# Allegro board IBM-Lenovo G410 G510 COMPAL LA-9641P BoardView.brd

Outline 212.65 x 184.36 mm; copper layers: TOP, VCC, IN1, IN2, GND, BOTTOM. Coordinates in mm from the lower left corner of the outline.
Outline path: 126,40.45 126,23.8 ; 126,40.45 arc(126.88,42.57) 129,43.45 ; 126,40.45 126,23.8 ; 126,23.8 arc(126.88,21.68) 129,20.8 ; 129,43.45 133.63,43.45 ; 129,43.45 133.63,43.45 ; 133.63,43.45 arc(134.34,43.74) 134.63,44.45 ; 129,20.8 176.5,20.8 ; 129,20.8 176.5,20.8 ; 176.5,20.8 arc(178.62,21.68) 179.5,23.8 ; 134.63,50.59 134.63,44.45 ; 134.63,50.59 arc(135.51,52.71) 137.63,53.59 ; 134.63,50.59 134.63,44.45 ; 137.63,53.59 142,53.59 ; 137.63,53.59 142,53.59 ; 142,53.59 arc(144.12,52.71) 145,50.59 ; 145,50.59 145,41.4 ; 145,50.59 145,41.4 ; 145,41.4 arc(145.29,40.69) 146,40.4 ; 146,40.4 163.7,40.4 ; 146,40.4 163.7,40.4 ; 163.7,40.4 arc(164.41,40.69) 164.7,41.4 ; 164.7,50.59 164.7,41.4 ; 164.7,50.59 arc(165.58,52.71) 167.7,53.59 ; 164.7,50.59 164.7,41.4 ; 167.7,53.59 170.7,53.59 ; 167.7,53.59 170.7,53.59 ; 170.7,53.59 arc(172.82,52.71) 173.7,50.59 ; 173.7,50.59 173.7,37.65 ; 173.7,50.59 173.7,37.65 ; 173.7,37.65 arc(173.99,36.94) 174.7,36.65 ; 174.7,36.65 176.5,36.65 ; 174.7,36.65 176.5,36.65 ; 176.5,36.65 arc(178.62,35.77) 179.5,33.65 ; 179.5,33.65 179.5,23.8 ; 179.5,33.65 179.5,23.8 ; 0,107.15 arc(0.29,107.86) 1,108.15 3.65,108.15 3.65,110.15 5.05,110.15 arc(6.05,111.15) 5.05,112.15 5.05,125.15 arc(6.05,126.15) 5.05,127.15 3.65,127.15 3.65,130 arc(3.94,130.71) 4.65,131 34.7,131 arc(35.41,131.29) 35.7,132 arc(35.99,132.71) 36.7,133 61.54,133 arc(62.25,133.29) 62.54,134 62.54,134.39 arc(62.74,134.98) 63.25,135.34 arc(68.65,137.48) 73.62,140.47 arc(88.26,151.25) 95.65,167.87 arc(95.99,168.47) 96.64,168.71 106.23,168.71 arc(106.93,169) 107.23,169.71 107.23,178.5 arc(107.52,179.21) 108.23,179.5 172.75,179.5 arc(173.46,179.79) 173.75,180.5 173.75,181.36 arc(174.04,182.07) 174.75,182.36 175.75,182.36 arc(176.46,182.65) 176.75,183.36 arc(177.04,184.07) 177.75,184.36 207.5,184.36 arc(208.21,184.07) 208.5,183.36 208.5,180.5 arc(208.79,179.79) 209.5,179.5 212.65,179.5 212.65,139.05 209.69,136.09 arc(209.37,135.88) 208.99,135.8 204.1,135.8 arc(203.39,135.51) 203.1,134.8 203.1,108.25 202.1,108.25 202.1,77.25 203.1,77.25 203.1,66.95 203.5,66.95 203.5,37.95 203.1,37.95 203.1,30.2 arc(203.39,29.49) 204.1,29.2 212.65,29.2 212.65,5.15 211.4,5.15 arc(210.41,4.74) 210,3.75 210,1.92 arc(209.56,1.55) 209.4,1 209.4,0 27.33,0 arc(26.77,0.58) 26,0.8 25,0.8 arc(24.23,0.58) 23.67,0 5.65,0 arc(5.14,0.22) 4.6,0.3 3.65,0.3 arc(1.53,1.18) 0.65,3.3 0.65,5.13 arc(0.94,5.83) 1.65,6.13 12.2,6.13 12.2,16.38 1.65,16.38 arc(0.94,16.67) 0.65,17.38 0.65,19.31 arc(0.94,20.02) 1.65,20.31 12.02,20.31 arc(13.02,21.31) 12.02,22.31 12.02,31.81 arc(13.02,32.81) 12.02,33.81 3.37,33.81 arc(2.66,34.1) 2.37,34.81 2.37,40.31 arc(2.66,41.02) 3.37,41.31 12.02,41.31 arc(13.02,42.31) 12.02,43.31 12.02,52.81 arc(13.02,53.81) 12.02,54.81 2.24,54.81 arc(1.53,55.1) 1.24,55.81 1.24,60.31 arc(1.53,61.02) 2.24,61.31 7.34,61.31 arc(8.34,60.31) 9.34,61.31 9.34,76.81 arc(8.34,77.81) 7.34,76.81 1.1,76.81 arc(0.39,77.1) 0.1,77.81 0.1,80.29 arc(0.39,80.99) 1.1,81.29 8.7,81.29 arc(10.41,80.58) 9.7,82.29 9.7,96.88 arc(10.41,98.59) 8.7,97.88 1,97.88 arc(0.29,98.18) 0,98.88 0,107.15

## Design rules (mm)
net group CLK_PCIE_VGA: nets CLK_PCIE_VGA CLK_PCIE_VGA#
net group CLK_PCIE_VGA_R: nets CLK_PCIE_VGA#_R CLK_PCIE_VGA_R
net group CLKA0: nets CLKA0 CLKA0#
net group CLKA1: nets CLKA1 CLKA1#
net group CLKB0: nets CLKB0 CLKB0#
net group CLKB1: nets CLKB1 CLKB1#
net group DDR_A_DQS0: nets DDR_A_DQS0 DDR_A_DQS#0
net group DDR_A_DQS1: nets DDR_A_DQS1 DDR_A_DQS#1
net group DDR_A_DQS2: nets DDR_A_DQS2 DDR_A_DQS#2
net group DDR_A_DQS3: nets DDR_A_DQS3 DDR_A_DQS#3
net group DDR_A_DQS4: nets DDR_A_DQS4 DDR_A_DQS#4
net group DDR_A_DQS5: nets DDR_A_DQS5 DDR_A_DQS#5
net group DDR_A_DQS6: nets DDR_A_DQS6 DDR_A_DQS#6
net group DDR_A_DQS7: nets DDR_A_DQS7 DDR_A_DQS#7
net group DDR_B_DQS0: nets DDR_B_DQS0 DDR_B_DQS#0
net group DDR_B_DQS1: nets DDR_B_DQS1 DDR_B_DQS#1
net group DDR_B_DQS2: nets DDR_B_DQS2 DDR_B_DQS#2
net group DDR_B_DQS3: nets DDR_B_DQS3 DDR_B_DQS#3
net group DDR_B_DQS4: nets DDR_B_DQS4 DDR_B_DQS#4
net group DDR_B_DQS5: nets DDR_B_DQS5 DDR_B_DQS#5
net group DDR_B_DQS6: nets DDR_B_DQS6 DDR_B_DQS#6
net group DDR_B_DQS7: nets DDR_B_DQS7 DDR_B_DQS#7
net group DIFFPAIR0: nets N25318268 N25318300
net group DMI_CRX_PTX_0: nets DMI_CRX_PTX_N0 DMI_CRX_PTX_P0
net group DMI_CRX_PTX_1: nets DMI_CRX_PTX_N1 DMI_CRX_PTX_P1
net group DMI_CRX_PTX_2: nets DMI_CRX_PTX_N2 DMI_CRX_PTX_P2
net group DMI_CRX_PTX_3: nets DMI_CRX_PTX_N3 DMI_CRX_PTX_P3
net group DMI_CTX_PRX_0: nets DMI_CTX_PRX_N0 DMI_CTX_PRX_P0
net group DMI_CTX_PRX_1: nets DMI_CTX_PRX_N1 DMI_CTX_PRX_P1
net group DMI_CTX_PRX_2: nets DMI_CTX_PRX_N2 DMI_CTX_PRX_P2
net group DMI_CTX_PRX_3: nets DMI_CTX_PRX_N3 DMI_CTX_PRX_P3
net group EC_SMB_CK1: nets EC_SMB_CK1 EC_SMB_DA1
net group EC_SMCA: nets EC_SMCA EC_SMDA
net group EDP_CPU_AUX: nets EDP_CPU_AUX EDP_CPU_AUX#
net group EDP_CPU_AUX_R: nets EDP_CPU_AUX#_R EDP_CPU_AUX_R
net group EDP_CPU_LANE_0: nets EDP_CPU_LANE_N0 EDP_CPU_LANE_P0
net group EDP_CPU_LANE_0_R: nets EDP_CPU_LANE_N0_R EDP_CPU_LANE_P0_R
net group EDP_CPU_LANE_1: nets EDP_CPU_LANE_N1 EDP_CPU_LANE_P1
net group FDI_CTX_PRX_0: nets FDI_CTX_PRX_N0 FDI_CTX_PRX_P0
net group FDI_CTX_PRX_1: nets FDI_CTX_PRX_N1 FDI_CTX_PRX_P1
net group HDMI_CLK_CK: nets HDMI_CLK+_CK HDMI_CLK-_CK
net group HDMI_CLK_CONN: nets HDMI_CLK+_CONN HDMI_CLK-_CONN
net group HDMI_TX0_CK: nets HDMI_TX0+_CK HDMI_TX0-_CK
net group HDMI_TX0_CONN: nets HDMI_TX0+_CONN HDMI_TX0-_CONN
net group HDMI_TX1_CK: nets HDMI_TX1+_CK HDMI_TX1-_CK
net group HDMI_TX1_CONN: nets HDMI_TX1+_CONN HDMI_TX1-_CONN
net group HDMI_TX2_CK: nets HDMI_TX2+_CK HDMI_TX2-_CK
net group HDMI_TX2_CONN: nets HDMI_TX2+_CONN HDMI_TX2-_CONN
net group HDMICLK_NB: nets HDMICLK_NB HDMIDAT_NB
net group HDMICLK_R: nets HDMICLK_R HDMIDAT_R
net group HP: nets HP_L HP_R
net group HPOUT: nets HPOUT_L HPOUT_R
net group LVDS_A0: nets LVDS_A0 LVDS_A0#
net group LVDS_A1: nets LVDS_A1 LVDS_A1#
net group LVDS_A2: nets LVDS_A2 LVDS_A2#
net group LVDS_ACLK: nets LVDS_ACLK LVDS_ACLK#
net group M_CLK_DDR0: nets M_CLK_DDR0 M_CLK_DDR#0
net group M_CLK_DDR1: nets M_CLK_DDR1 M_CLK_DDR#1
net group M_CLK_DDR2: nets M_CLK_DDR2 M_CLK_DDR#2
net group M_CLK_DDR3: nets M_CLK_DDR3 M_CLK_DDR#3
net group MDI0: nets MDI0+ MDI0-
net group MDI1: nets MDI1+ MDI1-
net group MICB: nets MICB_L MICB_R
net group MIIC_SCL: nets MIIC_SCL MIIC_SDA
net group PCH_SMBCLK: nets PCH_SMBCLK PCH_SMBDATA
net group PCIE_CRX_C_GTX_0: nets PCIE_CRX_C_GTX_N0 PCIE_CRX_C_GTX_P0
net group PCIE_CRX_C_GTX_1: nets PCIE_CRX_C_GTX_N1 PCIE_CRX_C_GTX_P1
net group PCIE_CRX_C_GTX_2: nets PCIE_CRX_C_GTX_N2 PCIE_CRX_C_GTX_P2
net group PCIE_CRX_C_GTX_3: nets PCIE_CRX_C_GTX_N3 PCIE_CRX_C_GTX_P3
net group PCIE_CRX_C_GTX_4: nets PCIE_CRX_C_GTX_N4 PCIE_CRX_C_GTX_P4
net group PCIE_CRX_C_GTX_5: nets PCIE_CRX_C_GTX_N5 PCIE_CRX_C_GTX_P5
net group PCIE_CRX_C_GTX_6: nets PCIE_CRX_C_GTX_N6 PCIE_CRX_C_GTX_P6
net group PCIE_CRX_C_GTX_7: nets PCIE_CRX_C_GTX_N7 PCIE_CRX_C_GTX_P7
net group PCIE_CRX_GTX_0: nets PCIE_CRX_GTX_N0 PCIE_CRX_GTX_P0
net group PCIE_CRX_GTX_1: nets PCIE_CRX_GTX_N1 PCIE_CRX_GTX_P1
net group PCIE_CRX_GTX_2: nets PCIE_CRX_GTX_N2 PCIE_CRX_GTX_P2
net group PCIE_CRX_GTX_3: nets PCIE_CRX_GTX_N3 PCIE_CRX_GTX_P3
net group PCIE_CRX_GTX_4: nets PCIE_CRX_GTX_N4 PCIE_CRX_GTX_P4
net group PCIE_CRX_GTX_5: nets PCIE_CRX_GTX_N5 PCIE_CRX_GTX_P5
net group PCIE_CRX_GTX_6: nets PCIE_CRX_GTX_N6 PCIE_CRX_GTX_P6
net group PCIE_CRX_GTX_7: nets PCIE_CRX_GTX_N7 PCIE_CRX_GTX_P7
net group PCIE_CTX_GRX_0: nets PCIE_CTX_GRX_N0 PCIE_CTX_GRX_P0
net group PCIE_CTX_GRX_1: nets PCIE_CTX_GRX_N1 PCIE_CTX_GRX_P1
net group PCIE_CTX_GRX_2: nets PCIE_CTX_GRX_N2 PCIE_CTX_GRX_P2
net group PCIE_CTX_GRX_3: nets PCIE_CTX_GRX_N3 PCIE_CTX_GRX_P3
net group PCIE_CTX_GRX_4: nets PCIE_CTX_GRX_N4 PCIE_CTX_GRX_P4
net group PCIE_CTX_GRX_5: nets PCIE_CTX_GRX_N5 PCIE_CTX_GRX_P5
net group PCIE_CTX_GRX_6: nets PCIE_CTX_GRX_N6 PCIE_CTX_GRX_P6
net group PCIE_CTX_GRX_7: nets PCIE_CTX_GRX_N7 PCIE_CTX_GRX_P7
net group PCIE_CTX_GRX_C_0: nets PCIE_CTX_GRX_C_N0 PCIE_CTX_GRX_C_P0
net group PCIE_CTX_GRX_C_1: nets PCIE_CTX_GRX_C_N1 PCIE_CTX_GRX_C_P1
net group PCIE_CTX_GRX_C_2: nets PCIE_CTX_GRX_C_N2 PCIE_CTX_GRX_C_P2
net group PCIE_CTX_GRX_C_3: nets PCIE_CTX_GRX_C_N3 PCIE_CTX_GRX_C_P3
net group PCIE_CTX_GRX_C_4: nets PCIE_CTX_GRX_C_N4 PCIE_CTX_GRX_C_P4
net group PCIE_CTX_GRX_C_5: nets PCIE_CTX_GRX_C_N5 PCIE_CTX_GRX_C_P5
net group PCIE_CTX_GRX_C_6: nets PCIE_CTX_GRX_C_N6 PCIE_CTX_GRX_C_P6
net group PCIE_CTX_GRX_C_7: nets PCIE_CTX_GRX_C_N7 PCIE_CTX_GRX_C_P7
net group PCIE_PRX_C_DTX_3: nets PCIE_PRX_C_DTX_N3 PCIE_PRX_C_DTX_P3
net group QSA0: nets QSA0 QSA#0
net group QSA1: nets QSA1 QSA#1
net group QSA2: nets QSA2 QSA#2
net group QSA3: nets QSA3 QSA#3
net group QSA4: nets QSA4 QSA#4
net group QSA5: nets QSA5 QSA#5
net group QSA6: nets QSA6 QSA#6
net group QSA7: nets QSA7 QSA#7
net group QSB0: nets QSB0 QSB#0
net group QSB1: nets QSB1 QSB#1
net group QSB2: nets QSB2 QSB#2
net group QSB3: nets QSB3 QSB#3
net group QSB4: nets QSB4 QSB#4
net group QSB5: nets QSB5 QSB#5
net group QSB6: nets QSB6 QSB#6
net group QSB7: nets QSB7 QSB#7
net group SML1CLK: nets SML1CLK SML1DATA
net group SPK_L: nets SPK_L1- SPK_L2+
net group SPK_L_CONN: nets SPK_L1-_CONN SPK_L2+_CONN
net group SPK_R: nets SPK_R1- SPK_R2+
net group SPK_R_CONN: nets SPK_R1-_CONN SPK_R2+_CONN
net group TMDS_B_CLK_PCH: nets TMDS_B_CLK#_PCH TMDS_B_CLK_PCH
net group TMDS_B_DATA0_PCH: nets TMDS_B_DATA0#_PCH TMDS_B_DATA0_PCH
net group TMDS_B_DATA1_PCH: nets TMDS_B_DATA1#_PCH TMDS_B_DATA1_PCH
net group TMDS_B_DATA2_PCH: nets TMDS_B_DATA2#_PCH TMDS_B_DATA2_PCH
net group U2D2: nets U2DN2 U2DP2
net group U3RXD1: nets U3RXDN1 U3RXDP1
net group U3RXD2: nets U3RXDN2 U3RXDP2
net group U3TXD1: nets U3TXDN1 U3TXDP1
net group U3TXD1_L: nets U3TXDN1_L U3TXDP1_L
net group U3TXD2: nets U3TXDN2 U3TXDP2
net group U3TXD2_L: nets U3TXDN2_L U3TXDP2_L
net group USB3_RX1_: nets USB3_RX1_N USB3_RX1_P
net group USB3_RX2_: nets USB3_RX2_N USB3_RX2_P
net group USB3_TX1_: nets USB3_TX1_N USB3_TX1_P
net group USB3_TX2_: nets USB3_TX2_N USB3_TX2_P
net group USB20_0: nets USB20_N0 USB20_P0
net group USB20_1: nets USB20_N1 USB20_P1
net group USB20_2: nets USB20_N2 USB20_P2
net group USB20_3_R: nets USB20_N3_R USB20_P3_R
net group USB20_9: nets USB20_N9 USB20_P9
net group USB20_9_C: nets USB20_N9_C USB20_P9_C
net group USB20_10: nets USB20_N10 USB20_P10
net group USB20_11: nets USB20_N11 USB20_P11
net group USB20_11_R: nets USB20_N11_R USB20_P11_R
net group VGA_SMB_CK2: nets VGA_SMB_CK2 VGA_SMB_DA2
net group VRAMA-CS#: nets CSA0#_0 CSA1#_0
net group VRAMB-CS#: nets CSB0#_0 CSB1#_0
net group 12/13.5: nets BUF_CPU_RST# CPU_PLTRST# DDR3_DRAMRST# H_DRAMRST# H_PM_SYNC H_PM_SYNC_R H_PROCHOT# H_PROCHOT#_R
net group 18: nets H_PECI
net group CRT-DAC: nets BLUE DAC_BLU DAC_GRN DAC_RED GREEN RED
net group CRT-SYNC: nets CRT_HSYNC CRT_VSYNC JVGA_HS JVGA_VS
net group DDRA-ADD: nets DDR_A_BS0 DDR_A_BS1 DDR_A_BS2 DDR_A_CAS# DDR_A_MA0 DDR_A_MA1 DDR_A_MA2 DDR_A_MA3 DDR_A_MA4 DDR_A_MA5 DDR_A_MA6 DDR_A_MA7 DDR_A_MA8 DDR_A_MA9 DDR_A_MA10 DDR_A_MA11 DDR_A_MA12 DDR_A_MA13 DDR_A_MA14 DDR_A_MA15 DDR_A_RAS# DDR_A_WE#
net group DDRA-CTL: nets DDR_CKE0_DIMMA DDR_CKE1_DIMMA DDR_CS0_DIMMA# DDR_CS1_DIMMA# M_ODT0 M_ODT1
net group DDRA_D0: nets DDR_A_D0 DDR_A_D1 DDR_A_D2 DDR_A_D3 DDR_A_D4 DDR_A_D5 DDR_A_D6 DDR_A_D7
net group DDRA_D1: nets DDR_A_D8 DDR_A_D9 DDR_A_D10 DDR_A_D11 DDR_A_D12 DDR_A_D13 DDR_A_D14 DDR_A_D15
net group DDRA_D2: nets DDR_A_D16 DDR_A_D17 DDR_A_D18 DDR_A_D19 DDR_A_D20 DDR_A_D21 DDR_A_D22 DDR_A_D23
net group DDRA_D3: nets DDR_A_D24 DDR_A_D25 DDR_A_D26 DDR_A_D27 DDR_A_D28 DDR_A_D29 DDR_A_D30 DDR_A_D31
net group DDRA_D4: nets DDR_A_D32 DDR_A_D33 DDR_A_D34 DDR_A_D35 DDR_A_D36 DDR_A_D37 DDR_A_D38 DDR_A_D39
net group DDRA_D5: nets DDR_A_D40 DDR_A_D41 DDR_A_D42 DDR_A_D43 DDR_A_D44 DDR_A_D45 DDR_A_D46 DDR_A_D47
net group DDRA_D6: nets DDR_A_D48 DDR_A_D49 DDR_A_D50 DDR_A_D51 DDR_A_D52 DDR_A_D53 DDR_A_D54 DDR_A_D55
net group DDRA_D7: nets DDR_A_D56 DDR_A_D57 DDR_A_D58 DDR_A_D59 DDR_A_D60 DDR_A_D61 DDR_A_D62 DDR_A_D63
net group DDRB-ADD: nets DDR_B_BS0 DDR_B_BS1 DDR_B_BS2 DDR_B_CAS# DDR_B_MA0 DDR_B_MA1 DDR_B_MA2 DDR_B_MA3 DDR_B_MA4 DDR_B_MA5 DDR_B_MA6 DDR_B_MA7 DDR_B_MA8 DDR_B_MA9 DDR_B_MA10 DDR_B_MA11 DDR_B_MA12 DDR_B_MA13 DDR_B_MA14 DDR_B_MA15 DDR_B_RAS# DDR_B_WE#
net group DDRB-CTL: nets DDR_CKE2_DIMMB DDR_CKE3_DIMMB DDR_CS2_DIMMB# DDR_CS3_DIMMB# M_ODT2 M_ODT3
net group DDRB_D0: nets DDR_B_D0 DDR_B_D1 DDR_B_D2 DDR_B_D3 DDR_B_D4 DDR_B_D5 DDR_B_D6 DDR_B_D7
net group DDRB_D1: nets DDR_B_D8 DDR_B_D9 DDR_B_D10 DDR_B_D11 DDR_B_D12 DDR_B_D13 DDR_B_D14 DDR_B_D15
net group DDRB_D2: nets DDR_B_D16 DDR_B_D17 DDR_B_D18 DDR_B_D19 DDR_B_D20 DDR_B_D21 DDR_B_D22 DDR_B_D23
net group DDRB_D3: nets DDR_B_D24 DDR_B_D25 DDR_B_D26 DDR_B_D27 DDR_B_D28 DDR_B_D29 DDR_B_D30 DDR_B_D31
net group DDRB_D4: nets DDR_B_D32 DDR_B_D33 DDR_B_D34 DDR_B_D35 DDR_B_D36 DDR_B_D37 DDR_B_D38 DDR_B_D39
net group DDRB_D5: nets DDR_B_D40 DDR_B_D41 DDR_B_D42 DDR_B_D43 DDR_B_D44 DDR_B_D45 DDR_B_D46 DDR_B_D47
net group DDRB_D6: nets DDR_B_D48 DDR_B_D49 DDR_B_D50 DDR_B_D51 DDR_B_D52 DDR_B_D53 DDR_B_D54 DDR_B_D55
net group DDRB_D7: nets DDR_B_D56 DDR_B_D57 DDR_B_D58 DDR_B_D59 DDR_B_D60 DDR_B_D61 DDR_B_D62 DDR_B_D63
net group HDA: nets HDA_BIT_CLK HDA_BITCLK_AUDIO HDA_RST# HDA_RST_AUDIO# HDA_SDIN0 HDA_SDOUT_AUDIO HDA_SPKR HDA_SYNC HDA_SYNC_AUDIO
net group LAN-10/10: nets MDO0+ MDO0- MDO1+ MDO1-
net group LPC: nets LPC_AD0 LPC_AD1 LPC_AD2 LPC_AD3 LPC_FRAME# SERIRQ
net group PCIE: nets PCIE_PRX_DTX_N2 PCIE_PRX_DTX_N3 PCIE_PRX_DTX_P2 PCIE_PRX_DTX_P3 PCIE_PTX_C_DRX_N2 PCIE_PTX_C_DRX_N3 PCIE_PTX_C_DRX_P2 PCIE_PTX_C_DRX_P3 PCIE_PTX_DRX_N2 PCIE_PTX_DRX_N3 PCIE_PTX_DRX_P2 PCIE_PTX_DRX_P3
net group PLATFORM-CLK: nets CLK_BUF_BCLK CLK_BUF_BCLK# CLK_BUF_CKSSCD CLK_BUF_CKSSCD# CLK_BUF_DMI CLK_BUF_DMI# CLK_BUF_DOT96 CLK_BUF_DOT96# CLK_CPU_DMI CLK_CPU_DMI# CLK_CPU_DPLL CLK_CPU_DPLL# CLK_CPU_SSC_DPLL CLK_CPU_SSC_DPLL# CLK_PCIE_LAN CLK_PCIE_LAN# CLK_PCIE_WLAN CLK_PCIE_WLAN# CLK_PCIE_WLAN#_R CLK_PCIE_WLAN_R
net group SATA3: nets SATA_DTX_C_PRX_N4 SATA_DTX_C_PRX_N5 SATA_DTX_C_PRX_P4 SATA_DTX_C_PRX_P5 SATA_DTX_PRX_N4 SATA_DTX_PRX_N5_14 SATA_DTX_PRX_N5_15 SATA_DTX_PRX_P4 SATA_DTX_PRX_P5_14 SATA_DTX_PRX_P5_15 SATA_PTX_C_DRX_N4 SATA_PTX_C_DRX_N5 SATA_PTX_C_DRX_P4 SATA_PTX_C_DRX_P5 SATA_PTX_DRX_N4 SATA_PTX_DRX_N5_14 SATA_PTX_DRX_N5_15 SATA_PTX_DRX_P4 SATA_PTX_DRX_P5_14 SATA_PTX_DRX_P5_15
net group SINGLE-CLK: nets CLK_PCH_14M CLK_PCI_DB_R CLK_PCI_EC CLK_PCI_EC_R CLK_PCI_LPBACK CLK_PCI_LPBACK_R CLK_REQ_VGA# CLKREQ_LAN# CLKREQ_WLAN#
net group SMBUS: nets EC_SMB_CK2 EC_SMB_DA2 EDID_CLK EDID_DATA PCH_SML0CLK PCH_SML0DATA SMB_CLK_S3 SMB_DATA_S3
net group SPI: nets SPI_CLK_PCH_R SPI_HOLD# SPI_SB_CS1# SPI_SI SPI_WP#
net group USB2.0: nets U2DN1 U2DP1 USB20_N3 USB20_P3
net group VRAMA-ADD: nets A_BA0 A_BA1 A_BA2 MAA0 MAA1 MAA2 MAA3 MAA4 MAA5 MAA6 MAA7 MAA8 MAA9 MAA10 MAA11 MAA12 MAA13 MAA14 MAA15
net group VRAMA-CTL: nets CASA0# CASA1# CKEA0 CKEA1 DRAM_RST# ODTA0 ODTA1 RASA0# RASA1# WEA0# WEA1#
net group VRAMA-D0: nets DQMA0 MDA0 MDA1 MDA2 MDA3 MDA4 MDA5 MDA6 MDA7
net group VRAMA-D1: nets DQMA1 MDA8 MDA9 MDA10 MDA11 MDA12 MDA13 MDA14 MDA15
net group VRAMA-D2: nets DQMA2 MDA16 MDA17 MDA18 MDA19 MDA20 MDA21 MDA22 MDA23
net group VRAMA-D3: nets DQMA3 MDA24 MDA25 MDA26 MDA27 MDA28 MDA29 MDA30 MDA31
net group VRAMA-D4: nets DQMA4 MDA32 MDA33 MDA34 MDA35 MDA36 MDA37 MDA38 MDA39
net group VRAMA-D5: nets DQMA5 MDA40 MDA41 MDA42 MDA43 MDA44 MDA45 MDA46 MDA47
net group VRAMA-D6: nets DQMA6 MDA48 MDA49 MDA50 MDA51 MDA52 MDA53 MDA54 MDA55
net group VRAMA-D7: nets DQMA7 MDA56 MDA57 MDA58 MDA59 MDA60 MDA61 MDA62 MDA63
net group VRAMB-ADD: nets B_BA0 B_BA1 B_BA2 MAB0 MAB1 MAB2 MAB3 MAB4 MAB5 MAB6 MAB7 MAB8 MAB9 MAB10 MAB11 MAB12 MAB13 MAB14 MAB15
net group VRAMB-CTL: nets CASB0# CASB1# CKEB0 CKEB1 ODTB0 ODTB1 RASB0# RASB1# WEB0# WEB1#
net group VRAMB-D0: nets DQMB0 MDB0 MDB1 MDB2 MDB3 MDB4 MDB5 MDB6 MDB7
net group VRAMB-D1: nets DQMB1 MDB8 MDB9 MDB10 MDB11 MDB12 MDB13 MDB14 MDB15
net group VRAMB-D2: nets DQMB2 MDB16 MDB17 MDB18 MDB19 MDB20 MDB21 MDB22 MDB23
net group VRAMB-D3: nets DQMB3 MDB24 MDB25 MDB26 MDB27 MDB28 MDB29 MDB30 MDB31
net group VRAMB-D4: nets DQMB4 MDB32 MDB33 MDB34 MDB35 MDB36 MDB37 MDB38 MDB39
net group VRAMB-D5: nets DQMB5 MDB40 MDB41 MDB42 MDB43 MDB44 MDB45 MDB46 MDB47
net group VRAMB-D6: nets DQMB6 MDB48 MDB49 MDB50 MDB51 MDB52 MDB53 MDB54 MDB55
net group VRAMB-D7: nets DQMB7 MDB56 MDB57 MDB58 MDB59 MDB60 MDB61 MDB62 MDB63
nets with their own width: min track width 0.102; nets +VSB
nets with their own width: min track width 0.254; nets +MICBIASB +MICBIASC EXT_MIC GNDA MIC_IN N19871308 N25274724 N25274821 REMOTE1+ REMOTE1- THERM_D+ THERM_D-
nets with their own width: min track width 0.305; nets PCH_PCIE_RCOMP PEG_RCOMP SM_RCOMP0 SM_RCOMP1 SM_RCOMP2
nets with their own width: min track width 0.381; nets +VREFC_A0 +VREFC_A1 +VREFC_A2 +VREFC_A3 +VREFC_B0 +VREFC_B1 +VREFC_B2 +VREFC_B3
nets with their own width: min track width 0.406; nets VCCSENSE VCCSENSE_VGA VSSSENSE VSSSENSE_VGA
nets with their own width: min track width 0.508; nets +1.1_AVDDL +1.1_DVDDL +1.05V_+1.5V_RUN +1.5VGS +1.05VS +1.5VS +1.7_VDDCT +1.35V +2.7_AVDDH +3V_LAN +3V_PCH +3V_ROM +3VALW +3VALW_EC +3VGS +3VLP +3VS +3VS_TS +5VALW +5VS +CHGRTC +CHGRTC_R +EC_VCCA +LDO_1.8V +PCH_USB_DCPSUS3 +PCH_VCCCLK +PCH_VCCDSW +PCH_VCCSST +PCH_VPROC +RTCBATT +RTCVCC +V18R +VCCIO_OUT +VCCST +VREF_CA +VREF_CA_R +VREF_DQ_DIMMA +VREF_DQ_DIMMB APPLE_MIC B+ CHASSIS1_GND ECAGND EDP_COMP GND MCT N19871378 NOKIA_MIC PCH_ENVDD PHASE1_VGA PHASE2_VGA UGATE1_VGA UGATE2_VGA
nets with their own width: min track width 1.016; nets +5V_ODD HGNDA HGNDB N35039154
nets with their own width: min track width 1.524; nets +3VS_PS +DP_V33 +LCDVDD_CONN +LEDVDD +SWR_LX +SWR_V12 +SWR_VDD TL_ENVDD
nets with their own width: min track width 2.032; nets +USB3_VCCA +USB_VCCB

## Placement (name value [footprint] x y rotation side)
C4  -  [C_0402]  86.57 143.22 270 bottom
C6  -  [C_0402]  10.32 115.17 0 top
C9  -  [C_0402]  90.91 112.92 0 bottom
C10  -  [C_0402]  92.66 111.54 0 bottom
C11  -  [C_0402]  90.88 110.24 0 bottom
C12  -  [C_0402]  92.64 108.89 0 bottom
C13  -  [C_0402]  90.87 107.37 0 bottom
C14  -  [C_0402]  92.67 106.17 0 bottom
C15  -  [C_0402]  90.93 104.87 0 bottom
C16  -  [C_0402]  90.93 103.08 0 bottom
C25  -  [C_0402]  90.93 112.03 0 bottom
C26  -  [C_0402]  92.64 110.66 0 bottom
C27  -  [C_0402]  90.88 109.33 0 bottom
C28  -  [C_0402]  92.62 108 0 bottom
C29  -  [C_0402]  90.89 106.46 0 bottom
C30  -  [C_0402]  92.68 105.28 0 bottom
C31  -  [C_0402]  90.93 103.99 0 bottom
C32  -  [C_0402]  90.93 102.19 0 bottom
C35  -  [C_0402]  94.32 89.01 0 top
C37  -  [C_0402]  73.95 36.29 0 top
C39  -  [C_0402]  30.78 57.81 270 top
C40  -  [C_0402]  31.84 45.07 270 top
C41  -  [C_0402]  29.78 62.69 0 bottom
C42  -  [C_0402]  28.11 65.49 0 bottom
C43  -  [C_0402]  28.11 64.58 0 bottom
C44  -  [C_0402]  29.79 61.65 0 bottom
C45  -  [C_0402]  29.79 60.75 0 bottom
C46  -  [C_0402]  26.31 66.86 0 bottom
C47  -  [C_0402]  26.31 65.96 0 bottom
C48  -  [C_0402]  29.78 63.59 0 bottom
C53  -  [C_0402]  87.83 99.42 90 top
C54  -  [C_0603]  58.83 92.56 90 top
C55  -  [C_0603]  70.53 92.55 90 top
C56  -  [C_0603]  74.54 92.56 90 top
C57  -  [C_0603]  66.42 92.55 90 top
C58  -  [C_0603]  62.51 92.56 90 top
C59  -  [C_MP2VLPS330MC4R2]  49.57 64.11 0 top
C60  -  [C_0805]  76.44 92.45 90 top
C61  -  [C_0805]  72.64 92.46 90 top
C62  -  [C_0805]  68.49 92.41 90 top
C63  -  [C_0805]  64.43 92.44 90 top
C64  -  [C_0805]  60.69 92.47 90 top
C65  -  [C_0603]  34.61 57.08 90 top
C66  -  [C_0402]  33.54 57.01 90 top
C67  -  [C_0402]  74.62 48.28 90 top
C68  -  [C_0603]  75.73 48.28 90 top
C69  -  [C_0603]  66.86 55.66 270 top
C70  -  [C_0603]  71.09 55.74 270 top
C71  -  [C_0603]  71.25 48.03 270 top
C72  -  [C_0603]  61.7 49.16 270 top
C73  -  [C_0603]  59.44 47.27 270 top
C74  -  [C_0603]  58.19 52.01 270 top
C75  -  [C_0603]  58.95 54.59 90 top
C76  -  [C_0603]  74.04 55.81 270 top
C77  -  [C_0402]  63.61 55.52 270 top
C78  -  [C_0402]  63.65 47.23 270 top
C79  -  [C_0402]  66.24 47.31 270 top
C80  -  [C_0402]  61.88 55.5 270 top
C81  -  [C_6SVPE220MX]  74.4 59.1 0 top
C82  -  [C_0402]  97.58 49.62 180 top
C83  -  [C_0402]  97.58 48.7 180 top
C84  -  [C_0402]  98.81 55.14 0 top
C85  -  [C_0402]  98.8 56.12 0 top
C86  -  [C_0603]  96.99 59.42 270 top
C87  -  [C_0402]  97.17 60.38 90 top
C88  -  [C_0603]  35.65 46.04 90 top
C89  -  [C_0402]  34.52 46.03 90 top
C90  -  [C_0402]  75.02 38.61 90 top
C91  -  [C_0603]  76.1 38.62 90 top
C92  -  [C_0603]  66.61 33.41 90 top
C93  -  [C_0402]  173.5 72.33 270 top
C94  -  [C_0603]  67.55 41.54 270 top
C95  -  [C_0603]  73.95 32.67 0 top
C96  -  [C_0603]  59.63 41.95 270 top
C97  -  [C_0603]  71.06 41.33 270 top
C98  -  [C_0603]  73.01 41.32 270 top
C99  -  [C_0603]  57.99 33.04 90 top
C100  -  [C_0402]  64.83 33.47 90 top
C101  -  [C_0402]  68.84 42.42 270 top
C102  -  [C_0402]  60.5 33.53 90 top
C103  -  [C_0402]  63.52 42.2 270 top
C104  -  [C_0402]  98.31 42.34 0 top
C105  -  [C_0402]  98.32 43.27 0 top
C106  -  [C_0402]  97.73 37.18 180 top
C107  -  [C_0402]  97.73 38.15 180 top
C108  -  [C_0603]  95.43 47.69 90 top
C109  -  [C_0402]  95.43 46.72 270 top
C110  -  [C_0603]  140.84 92.25 90 bottom
C111  -  [C_0402]  141.98 95.74 90 top
C112  -  [C_0402]  138.63 98.13 90 top
C113  -  [C_0603]  142.44 93.1 180 top
C114  -  [C_0402]  146.29 110.35 270 bottom
C115  -  [C_0603]  138.28 89.67 0 bottom
C116  -  [C_0402]  145.33 110.35 270 bottom
C118  -  [C_0402]  120.49 71.28 0 top
C119  -  [C_0402]  119.58 71.27 180 top
C120  -  [C_0402]  111.5 102.13 270 bottom
C122  -  [C_0402]  111.91 70.39 90 bottom
C123  -  [C_0402]  111.27 72.45 90 bottom
C124  -  [C_0402]  112.83 70.39 90 bottom
C125  -  [C_0402]  110.35 72.44 90 bottom
C126  -  [C_0402]  130.72 75.43 90 bottom
C127  -  [C_0402]  129.81 75.42 90 bottom
C128  -  [C_0603]  128.74 74.86 90 bottom
C129  -  [C_0603]  124.16 84.16 180 bottom
C130  -  [C_0402]  124.58 86.63 90 bottom
C131  -  [C_0402]  125.49 86.64 90 bottom
C132  -  [C_0402]  127.42 82.58 90 bottom
C133  -  [C_0603]  130.35 72.96 0 bottom
C134  -  [C_0402]  121.58 80.94 0 bottom
C135  -  [C_0402]  130.04 82.58 90 bottom
C136  -  [C_0402]  126.11 81.56 270 bottom
C137  -  [C_0805]  124.4 65.26 0 top
C138  -  [C_0402]  125.46 83.34 90 bottom
C139  -  [C_0402]  126.9 86.61 90 bottom
C140  -  [C_0603]  123.53 82.54 180 bottom
C143  -  [C_0402]  121.82 84.84 270 bottom
C144  -  [C_0402]  122.04 86.6 90 bottom
C145  -  [C_0402]  122.91 86.59 90 bottom
C146  -  [C_0402]  120.86 84.92 180 bottom
C147  -  [C_0603]  117.4 85.84 90 bottom
C149  -  [C_0402]  135.31 99.09 90 top
C152  -  [C_0402]  128.56 84.34 0 bottom
C153  -  [C_0402]  127.06 77.95 270 bottom
C154  -  [C_0402]  128.85 86.37 0 bottom
C155  -  [C_0402]  137.01 88.65 180 bottom
C156  -  [C_0402]  126.82 88.88 180 bottom
C157  -  [C_0402]  131.22 84.68 180 bottom
C158  -  [C_0402]  124.54 88.93 90 bottom
C159  -  [C_0402]  128.75 82.55 90 bottom
C160  -  [C_0402]  135.72 83.05 0 bottom
C162  -  [C_0402]  125.35 82.48 180 bottom
C163  -  [C_0402]  128.99 88.88 0 bottom
C164  -  [C_0402]  136.59 91.82 90 bottom
C165  -  [C_0402]  137.5 91.82 90 bottom
C166  -  [C_0402]  138.41 91.82 90 bottom
C167  -  [C_0402]  125.87 89.87 90 bottom
C169  -  [C_0402]  123.53 89.81 180 bottom
C170  -  [C_0402]  123.54 88.92 180 bottom
C171  -  [C_0402]  122.41 67.76 0 top
C172  -  [C_0603]  116.84 70.97 180 top
C173  -  [C_0402]  121.21 81.92 180 bottom
C174  -  [C_0402]  116.78 72.07 180 top
C175  -  [C_0402]  136.76 72.18 180 top
C176  -  [C_0402]  125.19 75.98 0 bottom
C177  -  [C_0402]  125.2 77.6 0 bottom
C178  -  [C_0402]  125.21 79.41 0 bottom
C179  -  [C_0402]  126.09 74.42 270 bottom
C180  -  [C_0402]  125.22 78.5 0 bottom
C181  -  [C_0402]  131.2 81.14 270 bottom
C182  -  [C_0402]  130.33 81.13 270 bottom
C183  -  [C_0402]  129.44 81.12 270 bottom
C184  -  [C_0402]  134.38 81.05 270 bottom
C185  -  [C_0603]  62.77 33.02 90 top
C186  -  [C_0402]  47.27 109.08 180 top
C190  -  [C_0402]  74.93 123.42 90 bottom
C191  -  [C_0402]  73.97 123.41 90 bottom
C192  -  [C_0402]  75.56 121.62 90 bottom
C193  -  [C_0402]  76.51 121.61 90 bottom
C411  -  [C_0402]  12.61 124.44 90 bottom
C412  -  [C_0402]  14.59 124.5 90 bottom
C492  -  [C_0402]  158.14 76.98 180 top
C493  -  [C_0402]  163.59 72.29 180 top
C494  -  [C_0402]  134.97 100.2 90 bottom
C516  -  [C_0603]  92.81 146.36 0 bottom
C519  -  [C_0603]  97.45 142.1 270 bottom
C520  -  [C_0402]  100.13 138 270 bottom
C522  -  [C_0402]  13.95 108.8 0 bottom
C523  -  [C_0402]  12.7 108.79 180 bottom
C524  -  [C_0402]  10.94 108.82 180 bottom
C525  -  [C_0402]  13.95 112.75 0 bottom
C526  -  [C_0402]  12.7 112.74 180 bottom
C527  -  [C_0402]  10.94 112.76 180 bottom
C529  -  [C_0402]  14.54 114.03 0 top
C531  -  [C_0402]  14.55 113.13 0 top
C535  -  [C_0402]  168.06 72.3 0 top
C536  -  [C_0402]  47.27 100.67 180 top
C537  -  [C_0402]  10.32 114.22 0 top
C541  -  [C_0805]  99.22 151.36 0 bottom
C543  -  [C_0402]  14.33 71.52 0 top
C544  -  [C_0402]  15.03 66.51 180 top
C547  -  [C_0402]  206.57 167.03 90 top
C548  -  [C_0603]  205.48 166.68 90 top
C587  -  [C_0402]  150.89 72.08 90 top
C591  -  [C_0603]  102.32 165.84 180 bottom
C596  -  [C_0402]  147.24 109.46 90 bottom
C597  -  [C_0402]  148.19 109.46 90 bottom
C598  -  [C_0402]  164.38 118.42 180 top
C599  -  [C_0402]  164.39 117.46 180 top
C602  -  [C_0603]  164.51 121.72 180 top
C604  -  [C_0402]  196.68 58.99 90 bottom
C605  -  [C_0402]  99.21 122.58 270 bottom
C607  -  [C_0402]  196.75 52.13 0 bottom
C608  -  [C_0603]  195.53 58.77 90 bottom
C613  -  [C_0402]  193.02 51.16 0 bottom
C614  -  [C_0402]  193.05 50.21 0 bottom
C615  -  [C_0402]  193.1 48.11 0 bottom
C616  -  [C_0402]  193.09 47.16 0 bottom
C653  -  [C_0402]  158.14 76.08 180 top
C654  -  [C_0402]  178.82 79.48 0 top
C655  -  [C_0402]  178.82 78.59 0 top
C656  -  [C_0402]  157.96 89.63 270 top
C657  -  [C_0402]  178.72 84.04 0 top
C658  -  [C_0402]  178.72 84.95 0 top
C659  -  [C_0402]  157.05 89.63 270 top
C660  -  [C_0402]  180.58 80.95 0 top
C661  -  [C_0402]  173.19 93.64 270 top
C662  -  [C_0402]  175.37 92.75 90 top
C663  -  [C_0402]  162.79 92.82 90 top
C664  -  [C_0402]  167.17 72.32 270 top
C667  -  [C_0603]  174.83 72.2 270 top
C696  -  [C_0402]  181.73 91.78 270 top
C714  -  [C_MP6VL220MC6]  199.48 116.11 180 bottom
C720  -  [C_0603]  122.35 4.66 270 bottom
C721  -  [C_0603]  132.3 6.88 90 bottom
C722  -  [C_0603]  133.7 6.9 90 bottom
C723  -  [C_0603]  78.19 15.19 180 top
C724  -  [C_0603]  85.23 19.01 0 top
C725  -  [C_0603]  85.26 17.65 0 top
C726  -  [C_0402]  132.19 3.91 270 bottom
C727  -  [C_0402]  78.31 17.6 270 top
C736  -  [C_MP6VL220MC6]  19.5 34.12 0 bottom
C780  -  [C_0603]  144.32 91.12 90 top
C781  -  [C_0402]  150.86 88.17 90 top
C782  -  [C_0603]  150.98 91.31 0 top
C783  -  [C_0603]  145.65 91.13 90 top
C847  -  [C_0402]  24.03 47.11 180 bottom
C848  -  [C_0402]  24.86 25.95 180 bottom
C849  -  [C_0402]  24.04 46.22 180 bottom
C850  -  [C_0402]  24.85 25.05 180 bottom
C1322  -  [C_0402]  201 138.72 90 top
C1331  -  [C_0402]  202.05 145.42 90 top
CA1  -  [C_0603]  151.24 43.67 180 top
CA2  -  [C_0402]  152.24 44.69 270 top
CA3  -  [C_0603]  148.53 47.46 0 top
CA4  -  [C_0402]  151.26 48.62 270 top
CA5  -  [C_0402]  151.87 51.66 90 top
CA6  -  [C_0603]  150.73 51.67 90 top
CA7  -  [C_0402]  158.62 57.5 90 top
CA8  -  [C_0603]  154.16 54.72 90 top
CA9  -  [C_0402]  153.96 53.64 0 top
CA10  -  [C_0402]  160.89 46.86 270 top
CA11  -  [C_0402]  161.07 52.25 0 top
CA15  -  [C_0603]  161.79 46.4 0 top
CA16  -  [C_0603]  162.06 49.9 90 top
CA17  -  [C_0402]  161.02 50.01 90 top
CA18  -  [C_0603]  149.89 46.14 180 top
CA19  -  [C_0402]  156.85 53.58 90 top
CA20  -  [C_0402]  151.24 46.86 270 top
CA21  -  [C_0402]  157.72 53.57 90 top
CA22  -  [C_0603]  155.81 54.72 90 top
CA23  -  [C_0603]  158.99 54.59 90 top
CA24  -  [C_0603]  161.79 47.62 0 top
CA25  -  [C_0402]  160.89 47.85 90 top
CA26  -  [C_0402]  158.78 53.52 0 top
CA27  -  [C_0402]  149.37 50.39 0 top
CA28  -  [C_0402]  149.37 49.38 0 top
CA29  -  [C_0603]  152.76 53.71 90 top
CA30  -  [C_0603]  149.97 55.61 270 top
CA31  -  [C_0402]  22.6 16.19 270 bottom
CA32  -  [C_0402]  22.6 13.48 90 bottom
CA33  -  [C_0402]  22.15 11.28 90 bottom
CA34  -  [C_0402]  22.16 10.39 270 bottom
CA35  -  [C_0402]  151.24 54.2 90 top
CA36  -  [C_0402]  149.41 52.5 180 top
CA37  -  [C_0402]  162.92 55.12 270 top
CA38  -  [C_0402]  179.31 128.51 180 top
CA39  -  [C_0402]  180.19 128.51 0 top
CA40  -  [C_0402]  184.27 128.41 180 top
CA41  -  [C_0603]  157.95 42.85 90 top
CA42  -  [C_0402]  29.51 67.15 270 top
CA43  -  [C_0402]  185.18 128.42 0 top
CA44  -  [C_0402]  154.25 42.83 270 top
CA45  -  [C_0402]  162.03 56.13 270 top
CA46  -  [C_0402]  149.41 51.48 180 top
CA64  -  [C_0402]  148.95 58.79 270 top
CA65  -  [C_0402]  144.81 55.17 0 top
CA66  -  [C_0402]  159.21 41.91 180 top
CL1  -  [C_0402]  35.25 15.82 90 top
CL2  -  [C_0402]  36.14 16.74 270 top
CL3  -  [C_0603]  37.1 17.07 0 top
CL4  -  [C_0402]  31.44 21.52 180 top
CL5  -  [C_0402]  31.44 22.41 180 top
CL6  -  [C_0603]  31.96 20.42 180 top
CL7  -  [C_0402]  39.91 17.61 0 top
CL8  -  [C_0402]  30.28 31.66 90 top
CL9  -  [C_0402]  26.49 27.45 0 top
CL10  -  [C_0402]  31.18 31.68 90 top
CL11  -  [C_0402]  26.49 26.44 0 top
CL12  -  [C_0402]  39.24 23.77 90 top
CL13  -  [C_0402]  38.3 24.7 270 top
CL14  -  [C_0402]  37.41 24.7 270 top
CL15  -  [C_0603]  40.29 23.55 0 top
CL16  -  [C_0603]  40.29 24.82 0 top
CL17  -  [C_0402]  29.36 31.68 90 top
CL18  -  [C_0402]  33.55 32.14 0 top
CL19  -  [C_0402]  28.63 21.43 0 top
CL20  -  [C_0402]  37.47 27.61 0 top
CL21  -  [C_0402]  37.45 28.51 0 top
CL22  -  [C_0402]  27.38 28.45 180 top
CL23  -  [C_0402]  36.47 30.86 270 top
CL24  -  [C_0402]  37.46 31.49 0 top
CL25  -  [C_0402]  33.49 20.31 0 top
CL26  -  [C_0402]  33.49 21.2 0 top
CL28  -  [C_0402]  37.45 30.6 0 top
CL29  -  [C_0402]  37.48 29.39 0 top
CL30  -  [C_0603]  19.51 88.77 0 top
CL31  -  [C_0402]  27.89 81.96 0 bottom
CL61  -  [C_0603]  21.81 78.67 180 top
CL62  -  [C_0603]  9.7 102.92 270 top
CL63  -  [C_0603]  22.05 85.82 180 top
CL64  -  [C_0603]  13.32 78.51 90 top
CLRP2  -  [SHORTPADS]  141.53 91.78 180 top
CLRP3  -  [SHORTPADS]  137.14 90.27 270 bottom
CT1  -  [C_0603]  80.05 129.02 180 top
CT2  -  [C_0402]  79.98 130.09 180 top
CT3  -  [C_0402]  79.97 130.98 180 top
CT4  -  [C_0603]  87.77 125.15 270 top
CT5  -  [C_0402]  86.69 125.01 270 top
CT6  -  [C_0603]  85.62 125.22 270 bottom
CT7  -  [C_0402]  86.76 125.22 270 bottom
CT8  -  [C_0402]  89.99 128.99 0 bottom
CT9  -  [C_0603]  82.27 122.92 180 top
CT10  -  [C_0402]  82.27 124.04 180 top
CT11  -  [C_0402]  86.69 135.13 90 top
CT12  -  [C_0402]  82.28 124.93 180 top
CV1  -  [C_0402]  127.62 118.64 270 bottom
CV2  -  [C_0402]  128.49 118.64 270 bottom
CV3  -  [C_0402]  126.32 120.64 270 bottom
CV4  -  [C_0402]  127.22 120.63 270 bottom
CV5  -  [C_0402]  125.15 118.65 270 bottom
CV6  -  [C_0402]  126.03 118.65 270 bottom
CV7  -  [C_0402]  124.01 120.63 270 bottom
CV8  -  [C_0402]  124.89 120.63 270 bottom
CV9  -  [C_0402]  123.68 118.66 270 bottom
CV10  -  [C_0402]  122.79 118.67 270 bottom
CV11  -  [C_0402]  122.48 120.63 270 bottom
CV12  -  [C_0402]  121.59 120.63 270 bottom
CV13  -  [C_0402]  121.19 118.67 270 bottom
CV14  -  [C_0402]  120.29 118.68 270 bottom
CV15  -  [C_0402]  120.01 120.63 270 bottom
CV16  -  [C_0402]  119.12 120.63 270 bottom
CV17  -  [C_0402]  142.17 129.4 90 top
CV18  -  [C_0402]  141.22 129.4 90 top
CV19  -  [C_0603]  141.98 128.49 270 top
CV20  -  [C_0402]  141.95 125.38 270 top
CV21  -  [C_0402]  142.87 125.38 270 top
CV22  -  [C_0603]  143.96 125.37 270 top
CV23  -  [C_0402]  153.31 144.91 270 bottom
CV26  -  [C_0402]  135.15 126.19 0 top
CV27  -  [C_0402]  151.47 133.78 0 top
CV28  -  [C_0402]  146.86 125.37 0 top
CV29  -  [C_0402]  137.84 126.19 180 top
CV30  -  [C_0603]  144.93 130.16 0 top
CV31  -  [C_0402]  144 130.31 180 top
CV32  -  [C_0402]  146.72 128.45 0 top
CV33  -  [C_0603]  122.1 152.62 90 top
CV34  -  [C_0402]  123.04 150.83 180 top
CV35  -  [C_0402]  123.24 149.92 270 top
CV36  -  [C_0402]  154.26 132.11 270 bottom
CV37  -  [C_0402]  154.26 129.36 90 bottom
CV38  -  [C_0603]  146.64 149.78 90 top
CV39  -  [C_0402]  147.72 149.71 90 top
CV40  -  [C_0402]  148.61 149.71 90 top
CV41  -  [C_0402]  153.26 149.45 0 bottom
CV42  -  [C_0402]  153.26 150.34 0 bottom
CV43  -  [C_0603]  154.36 152 0 bottom
CV44  -  [C_0402]  153.33 153.06 90 bottom
CV45  -  [C_0402]  154.34 153.06 90 bottom
CV46  -  [C_0603]  154.18 118.4 270 top
CV48  -  [C_0603]  142.19 114.81 90 top
CV49  -  [C_0603]  132.38 111.11 270 top
CV52  -  [C_0402]  150.36 122.33 180 top
CV53  -  [C_0402]  134.35 109.71 180 top
CV54  -  [C_0402]  133.94 134.49 0 top
CV55  -  [C_0402]  128.23 133.6 270 top
CV56  -  [C_0603]  150.08 131.46 270 top
CV57  -  [C_0603]  147.38 131.53 90 top
CV58  -  [C_0402]  144.01 128.66 270 top
CV59  -  [C_0402]  146.29 131.67 90 top
CV60  -  [C_0603]  115.84 137.03 270 top
CV61  -  [C_0402]  127.9 148.18 270 top
CV62  -  [C_0402]  139.07 127.53 0 top
CV63  -  [C_0402]  139.07 128.42 0 top
CV64  -  [C_0402]  139.06 126.53 0 top
CV65  -  [C_0603]  139.06 125.43 0 top
CV66  -  [C_B2]  116.82 173.25 90 bottom
CV67  -  [C_0603]  115.23 147.04 270 bottom
CV68  -  [C_0603]  115.79 137.68 90 bottom
CV69  -  [C_0603]  140.98 152.91 90 top
CV70  -  [C_0603]  142.69 153.3 90 top
CV71  -  [C_0402]  129.28 145.22 90 top
CV72  -  [C_0402]  103.61 132.54 90 bottom
CV73  -  [C_0402]  129.81 136.9 0 top
CV74  -  [C_0402]  129.52 138.93 0 top
CV75  -  [C_0402]  140.44 171.55 90 bottom
CV76  -  [C_0402]  130.16 147.83 270 top
CV77  -  [C_0402]  129.24 147.95 270 top
CV78  -  [C_0402]  131.19 147.86 270 top
CV79  -  [C_0402]  129.8 137.77 0 top
CV80  -  [C_0402]  148.44 131.43 270 top
CV81  -  [C_0402]  129.26 134.63 90 top
CV82  -  [C_0402]  130.18 134.64 90 top
CV83  -  [C_0402]  133.94 135.4 0 top
CV84  -  [C_0402]  128.33 134.63 90 top
CV85  -  [C_0603]  150.06 132.47 90 top
CV86  -  [C_0402]  148.45 132.34 90 top
CV87  -  [C_0402]  129.14 133.59 270 top
CV88  -  [C_0603]  130.65 133.45 270 top
CV89  -  [C_0603]  142.09 135.33 0 top
CV90  -  [C_0402]  140.71 135.28 180 top
CV91  -  [C_0402]  140.71 136.17 180 top
CV92  -  [C_0603]  142.29 139.13 180 top
CV94  -  [C_0402]  141.7 138.03 180 top
CV95  -  [C_0402]  141.69 137.12 180 top
CV96  -  [C_0402]  141.22 148.08 90 top
CV97  -  [C_0402]  142.11 148.08 90 top
CV98  -  [C_0402]  128.45 142.66 0 top
CV99  -  [C_0402]  128.75 141.79 270 top
CV100  -  [C_0402]  144.03 148.55 0 top
CV101  -  [C_0402]  153.32 148.52 270 bottom
CV102  -  [C_0402]  153.3 146.74 270 bottom
CV103  -  [C_0402]  103.64 135.15 180 top
CV104  -  [C_0402]  103.61 131.58 180 bottom
CV105  -  [C_0603]  131.11 111.11 270 top
CV106  -  [C_0402]  115.65 129.73 90 top
CV107  -  [C_0402]  103.61 127.03 90 bottom
CV108  -  [C_0402]  103.63 139.37 270 bottom
CV109  -  [C_0402]  103.6 126.13 270 bottom
CV112  -  [C_0402]  115.59 152.98 270 bottom
CV113  -  [C_0402]  105.39 140.58 0 bottom
CV115  -  [C_0603]  157.98 172.77 270 bottom
CV116  -  [C_0603]  103.39 145.45 270 bottom
CV117  -  [C_0402]  115.65 132.61 270 top
CV118  -  [C_0402]  103.61 137.31 270 bottom
CV119  -  [C_0402]  103.61 134.45 90 bottom
CV120  -  [C_0402]  103.6 139.77 270 top
CV121  -  [C_0402]  126.87 174.9 90 top
CV122  -  [C_0402]  103.63 130.68 270 top
CV124  -  [C_0402]  137.04 174.88 90 top
CV125  -  [C_0402]  106.12 161.01 90 bottom
CV126  -  [C_0402]  103.59 149.17 180 bottom
CV127  -  [C_0402]  103.59 151.88 180 top
CV128  -  [C_0603]  104.01 160.98 90 bottom
CV129  -  [C_0402]  103.57 149.13 270 top
CV130  -  [C_0402]  105.16 161.02 90 top
CV132  -  [C_0402]  103.56 147.32 270 top
CV134  -  [C_0402]  105.16 161.03 90 bottom
CV135  -  [C_0402]  103.55 156.47 270 bottom
CV136  -  [C_0402]  103.55 152.92 270 bottom
CV138  -  [C_0603]  103.4 145.46 270 top
CV139  -  [C_0603]  105.3 140.75 0 top
CV141  -  [C_0402]  104.22 161.02 90 top
CV144  -  [C_0402]  103.55 158.25 270 bottom
CV145  -  [C_0402]  103.55 153.78 90 bottom
CV146  -  [C_0402]  105.21 143.8 0 top
CV147  -  [C_0402]  106.1 161.03 90 top
CV148  -  [C_0402]  115.6 154.89 90 top
CV149  -  [C_0402]  130.64 174.86 90 top
CV150  -  [C_0402]  126.87 174.89 90 bottom
CV152  -  [C_0402]  103.54 159.99 270 top
CV154  -  [C_0402]  115.65 133.45 90 top
CV155  -  [C_0402]  122.45 174.89 0 top
CV156  -  [C_0402]  130.53 174.88 0 bottom
CV158  -  [C_0402]  136.33 172.37 0 top
CV159  -  [C_0402]  124.19 174.89 0 top
CV160  -  [C_0402]  119.39 171.7 270 top
CV161  -  [C_0603]  128.25 175.05 0 bottom
CV162  -  [C_0603]  119.16 174.21 270 top
CV164  -  [C_0402]  115.6 150.3 90 bottom
CV165  -  [C_0402]  119.4 171.69 270 bottom
CV166  -  [C_0402]  132.25 174.88 0 bottom
CV167  -  [C_0402]  120.7 174.9 0 bottom
CV168  -  [C_0402]  122.45 174.89 0 bottom
CV169  -  [C_0402]  134.96 174.89 180 bottom
CV170  -  [C_0402]  131.54 174.85 90 top
CV171  -  [C_0402]  120.71 174.9 0 top
CV172  -  [C_0402]  149.59 174.87 90 top
CV173  -  [C_0402]  150.67 161.87 180 bottom
CV174  -  [C_0603]  140.69 172.44 90 top
CV175  -  [C_0402]  154.71 174.93 0 bottom
CV176  -  [C_0402]  156.82 174.92 180 top
CV177  -  [C_0402]  157.4 174.93 180 bottom
CV178  -  [C_0402]  155.03 174.88 180 top
CV179  -  [C_0402]  145.85 174.9 0 bottom
CV181  -  [C_0402]  142.62 174.86 90 top
CV183  -  [C_0402]  144.07 174.9 0 bottom
CV184  -  [C_0603]  119.15 174.19 270 bottom
CV185  -  [C_0603]  157.98 172.76 270 top
CV186  -  [C_0402]  152.92 174.93 0 bottom
CV187  -  [C_0402]  135.82 174.89 0 bottom
CV188  -  [C_0402]  136.12 174.89 90 top
CV189  -  [C_0402]  141.66 174.85 90 top
CV190  -  [C_0402]  151.44 174.89 180 top
CV191  -  [C_0402]  153.27 174.9 180 top
CV192  -  [C_0402]  143.2 174.9 180 bottom
CV193  -  [C_0402]  151.14 174.92 0 bottom
CV194  -  [C_0402]  149.39 174.91 0 bottom
CV195  -  [C_0402]  102.71 137.98 0 top
CV196  -  [C_0402]  102.65 149.14 270 top
CV197  -  [C_0402]  134.25 175.79 270 top
CV198  -  [C_0402]  144.99 175.78 270 top
D1  -  [CH751H-40PT_SOD323-2]  142.11 90.26 270 top
D15  -  [PSOT24C_SOT23-3]  192.38 93.72 0 bottom
D22  -  [AZC099-04SPR7G_SOT23-6]  19.38 39.95 180 bottom
D24  -  [PSOT24C_SOT23-3]  96.56 114.99 270 top
D25  -  [PJDLC05_SOT23-3]  199.1 155.39 0 top
D26  -  [DAN202UT106_SC70-3]  101.2 116.57 180 top
D27  -  [YSCLAMP0524P_SLP2510P8-10-9]  17.23 44.75 90 bottom
D28  -  [YSCLAMP0524P_SLP2510P8-10-9]  18.26 62.94 90 bottom
D29  -  [YSCLAMP0524P_SLP2510P8-10-9]  18.61 59.23 90 bottom
D30  -  [YSCLAMP0524P_SLP2510P8-10-9]  17.76 23.6 90 bottom
D31  -  [AZC099-04SPR7G_SOT23-6]  17.92 21.72 0 bottom
D32  -  [YSCLAMP0524P_SLP2510P8-10-9]  15.85 71.85 270 bottom
DA1  -  [AZ5125-02SPR7G_SOT23-3]  20.81 14.89 270 bottom
DA2  -  [AZ5125-02SPR7G_SOT23-3]  20.39 10.83 270 bottom
DA3  -  [AZC099-04SPR7G_SOT23-6]  180.83 132.06 270 top
DL1  -  [AZC099-04SPR7G_SOT23-6]  26.93 72.09 270 bottom
DLL1  -  [BS4200N-C-LV_SMB-F2]  21.94 91.79 180 top
DV1  -  [CH751H-40PT_SOD323-2]  152.34 127.3 270 top
FD1  -  [FIDUCIAL_C40M80]  207.32 171.27 0 top
FD2  -  [FIDUCIAL_C40M80]  26.2 4.59 180 bottom
FD3  -  [FIDUCIAL_C40M80]  26.22 4.58 0 top
FD4  -  [FIDUCIAL_C40M80]  207.4 171.31 180 bottom
H1  -  [H_3P8]  67.69 126.1 0 top
H2  -  [H_3P8]  41.84 80.51 0 top
H3  -  [H_3P8]  93.54 80.51 0 top
H4  -  [H_3P3]  104.5 120.48 0 top
H5  -  [H_3P3]  161.6 157.71 0 top
H7  -  [H_2P8]  83.4 3.55 0 top
H8  -  [H_2P8]  2.8 103.8 0 top
H10  -  [H_2P8]  19.5 3.75 0 top
H11  -  [H_2P8]  201.5 173.8 0 top
H12  -  [H_2P8]  194.52 125.18 0 top
H16  -  [H_2P5X3P5N]  205.15 2.55 0 top
H17  -  [H_3P0N]  207.5 174.8 0 top
H18  -  [H_2P8]  199.5 72.25 0 top
J1  -  [JUMP_43X118]  61.23 62.02 90 top
J6  -  [JUMP_43X79]  202.49 167.47 0 top
J9  -  [JUMP_43X79]  192.31 54.69 90 bottom
J10  -  [JUMP_43X79]  45.43 20.13 90 top
J11  -  [SHORTPADS]  170.32 65.95 90 top
J12  -  [SHORTPADS]  199.18 96.03 270 bottom
JBATT1  -  [SUYIN_200082GR007M229ZR_7P-T]  187.5 181.06 0 bottom
JBATT2  -  [SUYIN_200082GR007M229ZR_7P-T]  175 176.06 0 bottom
JCPU1  -  [INTEL_HASWELL_947P-T]  85.51 79.94 180 bottom
JCR1  -  [CVILU_CF06041H0RB-NH_4P]  203.83 22.75 90 top
JCRT1  -  [CONTE_80431-5K1-152_15P]  6.05 114.07 90 bottom
JDCIN1  -  [ACES_50312-00541-001_5P-T]  193.33 153.55 90 bottom
JDIMM1  -  [FOX_AS0A626-U8SN-7F_204P]  34.52 57.58 0 bottom
JDIMM2  -  [FOX_AS0A626-U4SN-7F_204P]  34.52 44.58 0 bottom
JFAN1  -  [ACES_85205-04001_4P]  96.76 161.43 250 bottom
JHDD1  -  [SUYIN_127043FB022G278ZR_22P]  142.99 121.24 180 bottom
JHDMI1  -  [SUYIN_100042GR019M23DZL_19P-T]  10.34 64.56 90 bottom
JHP1  -  [SINGA_2SJ2352-000131F_6P]  10.5 5.35 90 bottom
JKB1  -  [ACES_88514-3001_30P]  184.2 97.23 180 top
JKB2  -  [ACES_88514-2401_24P-T]  152.04 102.93 180 top
JLAN1  -  [SANTA_130456-121_8P]  11.77 86.02 90 bottom
JLED1  -  [HB_A091020-SAHR21_10P]  180.85 50.25 270 top
JLVDS1  -  [ACES_88341-3001_30P]  99.83 152.91 235 top
JODD1  -  [ALLTO_C18518-11305-L_13P-T]  200.76 43.07 270 bottom
JODD2  -  [HB_A051020-SAHR21_10P]  183.92 47.15 90 top
JP3  -  [ACES_85205-0400_4P]  185.78 32.05 90 top
JPWRB1  -  [ACES_88058-060N_6P]  101.95 122.89 270 top
JRTC1  -  [ACES_50271-0020N-001_2P]  208.15 20.35 90 bottom
JSPK1  -  [ACES_85205-04001_4P]  183.93 130.67 180 bottom
JTP1  -  [ACES_88058-060N_6P]  192.5 96.1 0 top
JTS1  -  [ACES_50208-00601-P01_6P]  205.99 146.31 90 top
JUSB1  -  [TAITW_PUBAU1-09FNLSCNN4H0_9P]  14.8 30.56 90 bottom
JUSB2  -  [TAITW_PUBAU1-09FNLSCNN4H0_9P]  14.8 51.56 90 bottom
JUSB3  -  [ACES_88058-060N_6P]  203.36 158.3 90 top
JWLN1  -  [BELLW_80003-8041_52P]  199.1 140.4 90 bottom
L30  -  [CHENG_MBK1608121YZF_2P]  13.96 109.95 90 bottom
L31  -  [CHENG_MBK1608121YZF_2P]  12.7 109.98 90 bottom
L32  -  [CHENG_MBK1608121YZF_2P]  10.94 109.97 90 bottom
L35  -  [KING_WCM-2012-900T_4P]  23.48 64.43 180 bottom
L36  -  [KING_WCM-2012-900T_4P]  28.22 60.84 180 bottom
L37  -  [KING_WCM-2012-900T_4P]  23.48 62.6 180 bottom
L38  -  [KING_WCM-2012-900T_4P]  28.22 62.66 180 bottom
L44  -  [L_FBM-11-160808_2P]  157.47 92.33 270 top
L45  -  [L_FBM-11-160808_2P]  156.55 87.35 0 top
L49  -  [KING_WCM-2012-900T_4P]  21.62 46.3 180 bottom
L50  -  [KING_WCM-2012-900T_4P]  21.63 44.41 180 bottom
L51  -  [KING_WCM-2012-900T_4P]  22.64 40.83 180 bottom
L53  -  [KING_WCM-2012-900T_4P]  22.47 25.08 180 bottom
L54  -  [KING_WCM-2012-900T_4P]  22.48 23.34 180 bottom
L55  -  [KING_WCM-2012-900T_4P]  23.13 20.02 180 bottom
L58  -  [KING_WCM-2012-900T_4P]  95.58 139.45 150 bottom
L66  -  [KING_WCM-2012-900T_4P]  200.35 151.65 90 top
L67  -  [KING_WCM-2012-900T_4P]  200.79 28.73 270 bottom
LA1  -  [KC_FBMA-L11-160808-121LMT_2P]  185.54 125.66 90 top
LA2  -  [KC_FBMA-L11-160808-121LMT_2P]  183.95 125.65 90 top
LA3  -  [KC_FBMA-L11-160808-121LMT_2P]  180.58 125.74 90 top
LA4  -  [KC_FBMA-L11-160808-121LMT_2P]  179.03 125.73 90 top
LED1  -  [LED_19-213A-T1D-CP2Q2HY-3T_2P]  141.68 1.6 0 top
LED2  -  [LED_19-213A-T1D-CP2Q2HY-3T_2P]  151.68 3.39 0 top
LED5  -  [LED_19-213A-T1D-CP2Q2HY-3T_2P]  151.68 1.6 0 top
LED6  -  [LED_19-213A-T1D-CP2Q2HY-3T_2P]  161.68 1.6 0 top
LH1  -  [MURAT_BLM18PG181SN1D_L0603_2P]  131.62 74.28 180 bottom
LH2  -  [MURAT_LQM18FN4R7M00D_2P]  115.54 69.62 0 top
LL1  -  [DELTA_SIA4012-4R7M_2P]  37.2 18.55 90 top
LL2  -  [KC_FBMA-L11160808601LMA10T_2P]  29.46 20.08 180 top
LL3  -  [KC_FBMA-L11160808601LMA10T_2P]  32.18 17.25 0 top
LT1  -  [KC_FBMA-L11-201209-221LMA30_2P]  83.1 128.87 0 bottom
LT2  -  [KC_FBMA-L11-201209-221LMA30_2P]  87.1 127.56 90 bottom
LT3  -  [CYNTE_PG031B-4R7MS_2P]  83.4 123.97 0 top
LV1  -  [R0402_0OHM]  143.09 128.64 270 top
LV2  -  [R0402_0OHM]  145.07 125.36 270 top
LV3  -  [R0402_0OHM]  145.78 127.73 90 top
LV4  -  [R0603_0OHM]  133.89 148.96 180 top
LV5  -  [R0402_0OHM]  149.53 150.63 270 top
LV6  -  [R0402_0OHM]  153.3 151.19 90 bottom
LV7  -  [R0603_0OHM]  140.69 124.19 180 top
LV8  -  [R0402_0OHM]  143.19 134.25 180 top
LV9  -  [R0402_0OHM]  143.61 136.41 90 top
LV10  -  [R0603_0OHM]  138.28 148.31 0 top
MIC1  -  [MIC_WM-64PCY_2P]  22.1 71.25 90 top
NOREF  -  []  72.75 -29.92 0 top
NOREF#2  -  []  41 210.42 0 top
NOREF#3  -  []  2.8 103.8 0 top
NOREF#4  -  []  211.4 3.75 0 top
NOREF#5  -  []  19.5 3.75 180 top
NOREF#6  -  []  41.84 80.51 0 top
NOREF#7  -  []  161.6 157.71 0 top
NOREF#8  -  []  201.5 173.8 0 top
NOREF#9  -  []  67.69 126.1 0 top
NOREF#10  -  []  69.83 25.07 0 top
NOREF#11  -  []  199.5 72.25 270 top
NOREF#12  -  []  93.54 80.51 0 top
NOREF#13  -  []  81.26 29.13 0 top
NOREF#14  -  []  141.08 10.08 0 top
NOREF#15  -  []  104.5 120.48 0 top
NOREF#16  -  []  140.44 15.29 0 top
NOREF#17  -  []  83.4 3.55 180 top
NOREF#18  -  []  194.52 125.18 0 top
NOREF#19  -  []  56.91 75.79 0 top
NOREF#20  -  []  158.73 9.07 180 bottom
NOREF#21  -  []  81.39 28.5 180 bottom
NOREF#22  -  []  157.72 14.65 180 bottom
PC101  -  [C_0402]  190.27 151.92 90 bottom
PC102  -  [C_0402]  189.34 151.92 90 bottom
PC103  -  [C_0402]  185.66 146.15 180 top
PC104  -  [C_0402]  185.65 147.06 180 top
PC105  -  [C_0402]  183.59 113.77 90 top
PC106  -  [C_0402]  187.18 119.24 180 top
PC107  -  [C_0402]  189.67 119.04 0 top
PC108  -  [C_0402]  195.95 78.61 180 top
PC109  -  [C_0402]  195.93 77.69 180 top
PC201  -  [C_0402]  180.77 171.06 0 top
PC202  -  [C_0402]  185.68 72.96 0 top
PC203  -  [C_0402]  167.85 170.66 180 top
PC207  -  [C_0402]  186.41 63.82 0 top
PC208  -  [C_0402]  183.46 63.79 0 top
PC209  -  [C_0402]  190.9 71.88 0 top
PC210  -  [C_0402]  188.78 73.91 270 top
PC211  -  [C_0603]  110.38 14.09 180 bottom
PC212  -  [C_0402]  110.42 16.67 180 bottom
PC213  -  [C_0402]  114.98 16.52 270 bottom
PC301  -  [C_0402]  186.49 162.11 180 top
PC302  -  [C_0603]  183.5 149.62 90 bottom
PC303  -  [C_0402]  193.08 167.23 270 top
PC304  -  [C_0402]  189.2 166.74 0 bottom
PC305  -  [C_0402]  188.92 172.34 270 top
PC306  -  [C_0402]  187.06 172.34 0 top
PC307  -  [C_0402]  189.58 165.8 270 bottom
PC308  -  [C_0402]  187.79 164.89 0 bottom
PC309  -  [C_0402]  186.16 172.34 270 top
PC310  -  [C_0805]  179.59 154.07 90 top
PC311  -  [C_0402]  186.92 165.74 270 bottom
PC312  -  [C_0603]  186.19 167.63 0 bottom
PC313  -  [C_0805]  181.33 169.03 270 top
PC314  -  [C_0603]  184.11 166.06 90 bottom
PC315  -  [C_0805]  172.26 161.86 0 top
PC316  -  [C_0805]  172.28 163.76 0 top
PC317  -  [C_0603]  183.97 163.22 180 top
PC318  -  [C_0805]  181.31 157.5 180 top
PC319  -  [C_0805]  172.28 165.54 0 top
PC320  -  [C_0603]  167.68 154.99 180 bottom
PC322  -  [C_0805]  168.21 169.25 180 top
PC323  -  [C_0805]  168.18 167.34 180 top
PC324  -  [C_0402]  162.89 165.97 270 top
PC402  -  [C_0603]  67.61 4.32 0 top
PC403  -  [C_0402]  63.58 5.41 270 bottom
PC404  -  [C_0402]  63.59 5.41 270 top
PC405  -  [C_0805]  62.91 7.04 180 top
PC406  -  [C_0805]  62.9 7.06 180 bottom
PC407  -  [C_0603]  112.07 4.25 90 top
PC408  -  [C_0805]  81.58 9.51 270 top
PC409  -  [C_0805]  79.8 9.51 270 top
PC410  -  [C_0805]  88.88 9.45 270 top
PC411  -  [C_0805]  83.42 9.51 270 top
PC412  -  [C_0805]  87.1 9.45 270 top
PC413  -  [C_0805]  85.26 9.45 270 top
PC414  -  [C_0603]  65.4 3.44 180 bottom
PC415  -  [C_0603]  68.77 12.66 180 top
PC416  -  [C_0805]  98.41 4.7 270 top
PC417  -  [C_0402]  97.01 4.57 270 top
PC418  -  [C_0402]  97.01 3.96 270 bottom
PC419  -  [C_0402]  101.75 8.35 0 top
PC420  -  [C_0805]  98.41 4.7 270 bottom
PC421  -  [C_0603]  99 8.25 90 top
PC422  -  [C_0603]  100.51 8.21 90 top
PC423  -  [C_0805]  117.21 4.83 270 bottom
PC424  -  [C_0805]  118.99 4.85 270 bottom
PC425  -  [C_0805]  117.59 6.64 180 bottom
PC426  -  [C_0805]  120.72 4.87 270 bottom
PC427  -  [C_0805]  117.64 8.55 180 bottom
PC428  -  [C_0805]  116.67 12.9 90 bottom
PC429  -  [C_0603]  101.62 4.24 0 top
PC430  -  [C_0603]  100.32 5.94 270 top
PC431  -  [C_0402]  103.58 8.14 0 top
PC432  -  [C_0402]  67.2 4.58 270 bottom
PC433  -  [C_0402]  62.29 5.36 270 top
PC434  -  [C_0402]  95.71 3.95 270 bottom
PC435  -  [C_0402]  66.47 6.55 90 bottom
PC501  -  [C_0805]  57.77 5.62 90 bottom
PC503  -  [C_0402]  29.29 8.91 90 top
PC504  -  [C_0805]  35.34 11.63 0 top
PC505  -  [C_0805]  35.36 13.41 0 top
PC506  -  [C_0402]  32.33 11.25 90 top
PC508  -  [C_0402]  29.26 7.99 270 top
PC509  -  [C_0402]  56.4 5.08 90 top
PC510  -  [C_0603]  31.76 3.25 270 top
PC511  -  [C_0603]  30.5 3.24 270 top
PC512  -  [C_0603]  37.99 6.75 270 top
PC513  -  [C_0402]  56.3 5.93 90 bottom
PC517  -  [C_0603]  45.84 2.98 180 bottom
PC520  -  [C_0805]  57.72 4.8 90 top
PC522  -  [C_FP-2R5ME331M-SLR]  50.88 16.37 180 top
PC601  -  [C_0603]  205.21 9.78 90 bottom
PC602  -  [C_0603]  196.65 9.17 0 top
PC603  -  [C_0402]  196.75 6.68 270 bottom
PC604  -  [C_0805]  194.51 6.79 270 bottom
PC605  -  [C_0603]  195.23 13.27 90 bottom
PC606  -  [C_0603]  194.83 11.26 180 bottom
PC607  -  [C_0402]  196.74 13.23 0 bottom
PC608  -  [C_0805]  201.26 14.76 270 bottom
PC609  -  [C_0805]  203.05 14.74 270 bottom
PC610  -  [C_0805]  197.7 20.52 180 top
PC611  -  [C_0805]  197.68 18.79 180 top
PC612  -  [C_0805]  197.68 16.99 180 top
PC613  -  [C_0603]  109.49 165.83 180 top
PC617  -  [C_0402]  195.85 6.66 270 bottom
PC618  -  [C_0805]  111.63 166.13 180 bottom
PC619  -  [C_0402]  115.18 170.19 180 top
PC620  -  [C_0805]  111.62 167.89 180 bottom
PC621  -  [C_0402]  177.43 126.08 270 top
PC622  -  [C_0805]  162.22 129.7 270 top
PC625  -  [C_0402]  113.8 172.91 270 top
PC626  -  [C_0805]  112.04 173.82 90 top
PC627  -  [C_0805]  175.14 126.35 270 top
PC628  -  [C_0603]  174.48 128.64 90 bottom
PC629  -  [C_0805]  160.46 129.69 270 top
PC630  -  [C_0603]  173.08 131.49 0 bottom
PC631  -  [C_0805]  164.01 129.7 270 top
PC632  -  [C_0603]  169.78 129.59 270 bottom
PC633  -  [C_0805]  165.78 129.72 270 top
PC634  -  [C_0603]  172.78 124.64 0 bottom
